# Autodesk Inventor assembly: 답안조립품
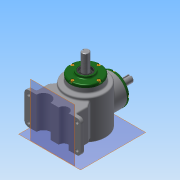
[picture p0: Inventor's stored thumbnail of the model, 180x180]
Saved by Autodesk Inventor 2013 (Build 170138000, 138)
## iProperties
Created: 2018-08
Part Number: 답안조립품
Document SubType Name: Assembly
Designer: Administrator
Author: Administrator
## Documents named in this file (14)
- C:\Users\Administrator\Desktop\480808V1011\답안조립품.iam
- C:\Users\Administrator\Desktop\480808V1011\본체.ipt
- C:\Users\Administrator\Desktop\480808V1011\메인 베벨기어.ipt
- C:\Users\Administrator\Desktop\480808V1011\메인 축.ipt
- 메인 축.ipt
- C:\Users\Administrator\Desktop\480808V1011\베어링 6203.ipt
- C:\Users\Administrator\Desktop\480808V1011\볼트 M4.ipt
- C:\Users\Administrator\Desktop\480808V1011\서브 베벨기어.ipt
- C:\Users\Administrator\Desktop\480808V1011\서브 축.ipt
- 서브 축.ipt
- C:\Users\Administrator\Desktop\480808V1011\오일실 17 32 8.ipt
- C:\Users\Administrator\Desktop\480808V1011\커버.ipt
- C:\Users\Administrator\Desktop\480808V1011\키 4x4.ipt
- C:\Users\Administrator\Desktop\480808V1011\키 5x5.ipt
